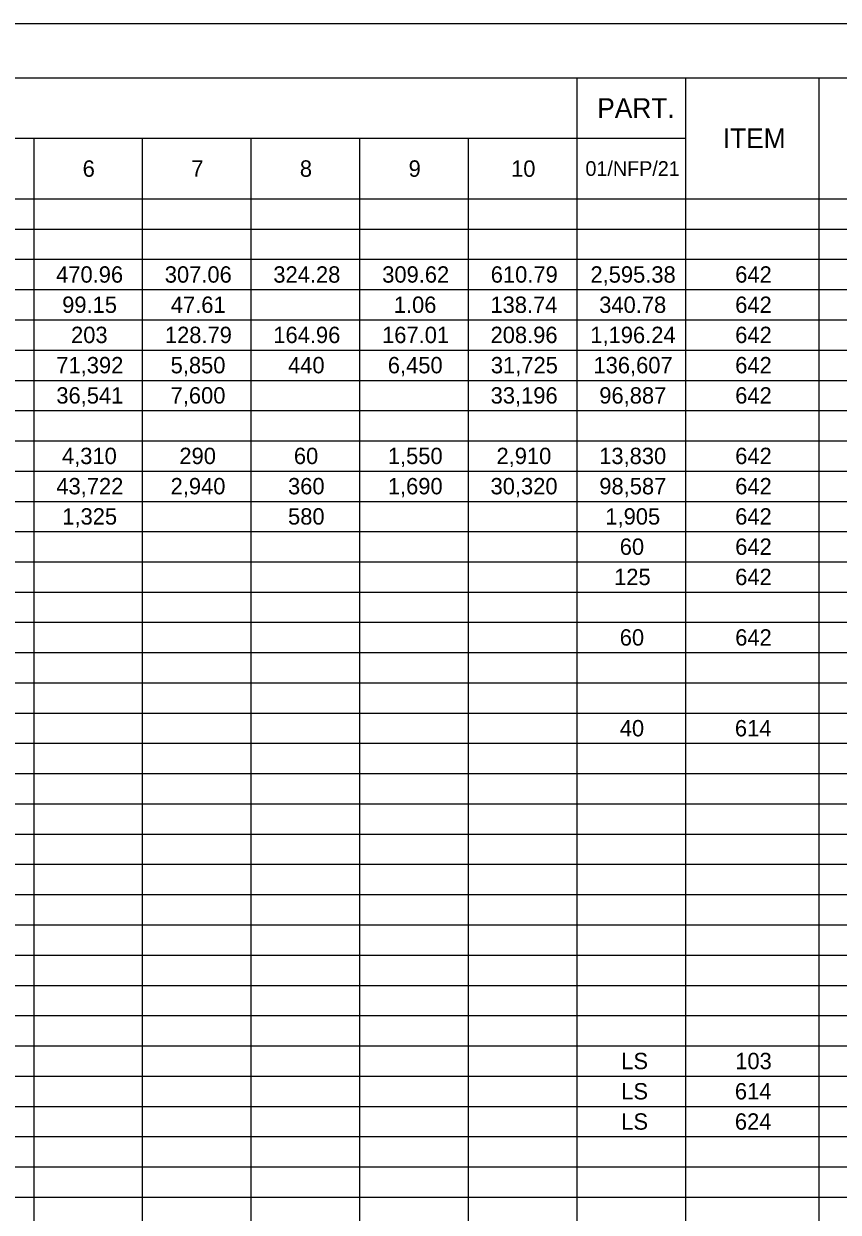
# Model space of a CAD drawing. Extents: x 0 to 34, y 0 to 22.
# Drawn here: x 9.44 to 16.98, y 11 to 22 of the extents above; entities that cross this region are included whole.
import ezdxf

# ---------------------------------------------------------------- set-up
doc = ezdxf.new("R2010")
doc.units = 0
for name, color, linetype in [('SH_Border', 7, 'Continuous'), ('SH_Cut_Line', 7, 'Continuous'), ('SH_Text', 7, 'Continuous')]:
    doc.layers.add(name, color=color, linetype=linetype)

msp = doc.modelspace()

# ---------------------------------------------------------------- linework, layer by layer
at = {"layer": 'SH_Border'}
msp.add_lwpolyline([(1.5, 21.5), (33.5, 21.5), (33.5, 0.5), (1.5, 0.5)], close=True, dxfattribs=at)
at = {"layer": 'SH_Cut_Line'}
msp.add_lwpolyline([(0, 0), (34, 0), (34, 22), (0, 22)], close=True, dxfattribs=at)
at = {"layer": 'SH_Text'}
for p, q in [((1.5, 21.5), (32, 21.5)), ((14.56, 21.5), (14.56, 0.502)), ((15.564, 21.5), (15.564, 0.502)), ((16.799, 21.5), (16.799, 0.502)), ((1.5, 20.94), (15.564, 20.94)), ((9.537, 20.94), (9.537, 0.502)), ((10.541, 20.94), (10.541, 0.502)), ((11.546, 20.94), (11.546, 0.502)), ((12.55, 20.94), (12.55, 0.502)), ((13.555, 20.94), (13.555, 0.502)), ((1.5, 20.38), (32, 20.38)), ((1.5, 20.1), (32, 20.1)), ((1.5, 19.82), (32, 19.82)), ((1.5, 19.54), (32, 19.54)), ((1.5, 19.26), (32, 19.26)), ((1.5, 18.98), (32, 18.98)), ((1.5, 18.7), (32, 18.7)), ((1.5, 18.42), (32, 18.42)), ((1.5, 18.14), (32, 18.14)), ((1.5, 17.86), (32, 17.86)), ((1.5, 17.58), (32, 17.58)), ((1.5, 17.3), (32, 17.3)), ((1.5, 17.021), (32, 17.021)), ((1.5, 16.741), (32, 16.741)), ((1.5, 16.461), (32, 16.461)), ((1.5, 16.181), (32, 16.181)), ((1.5, 15.901), (32, 15.901)), ((1.5, 15.621), (32, 15.621)), ((1.5, 15.341), (32, 15.341)), ((1.5, 15.061), (32, 15.061)), ((1.5, 14.781), (32, 14.781)), ((1.5, 14.501), (32, 14.501)), ((1.5, 14.221), (32, 14.221)), ((1.5, 13.941), (32, 13.941)), ((1.5, 13.661), (32, 13.661)), ((1.5, 13.381), (32, 13.381)), ((1.5, 13.101), (32, 13.101)), ((1.5, 12.821), (32, 12.821)), ((1.5, 12.541), (32, 12.541)), ((1.5, 12.261), (32, 12.261)), ((1.5, 11.981), (32, 11.981)), ((1.5, 11.701), (32, 11.701)), ((1.5, 11.421), (32, 11.421)), ((1.5, 11.141), (32, 11.141))]:
    msp.add_line(p, q, dxfattribs=at)

# ---------------------------------------------------------------- texts
for s, height, p in [('PART.', 0.1818, (14.749, 21.129)), ('ITEM', 0.1818, (15.91, 20.849)), ('6', 0.152, (9.989, 20.584)), ('7', 0.152, (10.994, 20.584)), ('8', 0.152, (11.998, 20.584)), ('9', 0.152, (13.004, 20.584)), ('10', 0.1515, (13.952, 20.584)), ('01/NFP/21', 0.1364, (14.64, 20.592)), ('470.96', 0.1515, (9.744, 19.604)), ('307.06', 0.1515, (10.749, 19.604)), ('324.28', 0.1515, (11.753, 19.604)), ('309.62', 0.1515, (12.76, 19.604)), ('610.79', 0.1515, (13.764, 19.604)), ('2,595.38', 0.1515, (14.686, 19.604)), ('642', 0.1515, (16.025, 19.604)), ('99.15', 0.1515, (9.8, 19.324)), ('47.61', 0.1515, (10.805, 19.324)), ('1.06', 0.1515, (12.867, 19.324)), ('138.74', 0.1515, (13.761, 19.324)), ('340.78', 0.1515, (14.767, 19.324)), ('642', 0.1515, (16.025, 19.324)), ('203', 0.1515, (9.882, 19.045)), ('128.79', 0.1515, (10.75, 19.045)), ('164.96', 0.1515, (11.753, 19.045)), ('167.01', 0.1515, (12.759, 19.045)), ('208.96', 0.1515, (13.762, 19.045)), ('1,196.24', 0.1515, (14.685, 19.045)), ('642', 0.1515, (16.025, 19.045)), ('71,392', 0.1515, (9.746, 18.765)), ('5,850', 0.1515, (10.803, 18.765)), ('440', 0.1515, (11.889, 18.765)), ('6,450', 0.1515, (12.812, 18.765)), ('31,725', 0.1515, (13.765, 18.765)), ('136,607', 0.1515, (14.714, 18.765)), ('642', 0.1515, (16.025, 18.765)), ('36,541', 0.1515, (9.746, 18.485)), ('7,600', 0.1515, (10.803, 18.485)), ('33,196', 0.1515, (13.763, 18.485)), ('96,887', 0.1515, (14.768, 18.485)), ('642', 0.1515, (16.025, 18.485)), ('4,310', 0.1515, (9.798, 17.925)), ('290', 0.1515, (10.884, 17.925)), ('60', 0.1515, (11.943, 17.925)), ('1,550', 0.1515, (12.812, 17.925)), ('2,910', 0.1515, (13.817, 17.925)), ('13,830', 0.1515, (14.767, 17.925)), ('642', 0.1515, (16.025, 17.925)), ('43,722', 0.1515, (9.746, 17.645)), ('2,940', 0.1515, (10.803, 17.645)), ('360', 0.1515, (11.889, 17.645)), ('1,690', 0.1515, (12.812, 17.645)), ('30,320', 0.1515, (13.762, 17.645)), ('98,587', 0.1515, (14.768, 17.645)), ('642', 0.1515, (16.025, 17.645)), ('1,325', 0.1515, (9.801, 17.365)), ('580', 0.1515, (11.889, 17.365)), ('1,905', 0.1515, (14.824, 17.365)), ('642', 0.1515, (16.025, 17.365)), ('60', 0.1515, (14.957, 17.085)), ('642', 0.1515, (16.025, 17.085)), ('125', 0.1515, (14.905, 16.805)), ('642', 0.1515, (16.025, 16.805)), ('60', 0.1515, (14.957, 16.245)), ('642', 0.1515, (16.025, 16.245)), ('40', 0.1515, (14.957, 15.405)), ('614', 0.1515, (16.022, 15.405)), ('LS', 0.1515, (14.971, 12.325)), ('103', 0.1515, (16.025, 12.325)), ('LS', 0.1515, (14.971, 12.045)), ('614', 0.1515, (16.022, 12.045)), ('LS', 0.1515, (14.971, 11.765)), ('624', 0.1515, (16.022, 11.765))]:
    msp.add_text(s, height=height, dxfattribs=at).set_placement(p)

doc.saveas('drawing.dxf')
